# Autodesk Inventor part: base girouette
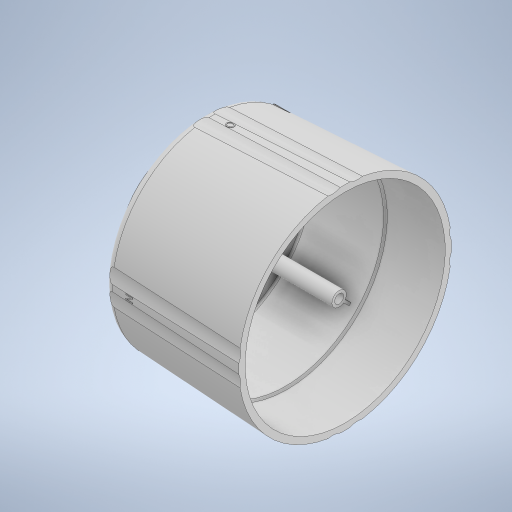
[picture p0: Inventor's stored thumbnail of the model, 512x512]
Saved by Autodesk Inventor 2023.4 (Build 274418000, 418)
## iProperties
Created: 2024-02
Part Number: base girouette
Material: Générique
Document SubType Name: Modeling
Designer: mel
Density: 1 g/cm^3
Appearance: Par défaut
Author: mel
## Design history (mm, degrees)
sketch "Esquisse1"
  geometry: L1 (1.75, 16.5)-(0, 16.5); L2 (0, 16.5)-(0, 15.5); L3 (6.57, 3)-(6.57, 15.5); L4 (6.57, 17.5)-(1.75, 17.5); L5 (1.75, 17.5)-(1.75, 16.5); L6 (45.5, 27.5)-(45.5, 29.25); L7 (45.5, 27.5)-(29.57, 27.5); L8 (30, 17.5)-(30, 16.5); L9 (9.57, 27)-(29.07, 27); L10 (30, 17.5)-(30, 16.5); L11 (9.07, 0)-(9.07, 27.382); L12 (45.5, 29.25)-(8.942, 27.375); L13 (29.57, 27.5)-(29.07, 27); L14 (29.57, 27.5)-(29.044, 27.5); L15 (0, 15.5)-(6.57, 15.5); L16 (-3.5, 0)-(9.07, 0) reference; L17 (0.5, 2.5)-(-3.5, 2.5); L18 (-3.5, 2.5)-(-3.5, 0); L19 (6.57, 3)-(0.5, 3); L20 (0.5, 3)-(0.5, 2.5); L21 (1.75, 2.5)-(4.57, 2.5); L22 (6.57, 24.878)-(6.57, 17.5); L23 (6.57, 15.5)-(6.57, 3); A1 r 2.5 centre (9.07, 24.878) between (8.942, 27.375) and (6.57, 24.878); A2 r 0.5 centre (9.57, 26.5) between (9.57, 27) and (9.07, 26.5); 3 further points
  constraints: 46 end point, 7 point on line, 6 horizontal, 6 parallel, 5 tangent, 4 perpendicular, 4 point on circle, 2 centre point
  dimensions: "d1" = 15.5 distance between parallel lines of L6 L8; "d5" = 27.25 vertical distance of point (6.5, 27.25) point (0, 0); "d6" = 2.5 radius of A1; "d7" = 0.5 radius of A2; "d8" = 135 deg angle of L13 L14; "d12" = 2.5 distance between parallel lines of L11 L3; "d14" = 15.5 distance from line of L15 point (0, 0); "d15" = 2.5 distance between parallel lines of L17 L16; "d17" = 4 distance between parallel lines of L20 L18; "d18" = 3 distance between parallel lines of L16 L19; "d22" = 27.5 distance between parallel lines of L7 L16; "d23" = 29.25 distance from line of L16 L6.end; "d29" = 2.93567 deg angle of L12 L16; "d63" = 27 distance between parallel lines of L16 L9; "d69" = 20 distance from line of L9.end L11
revolve "Révolution1" sketch "Esquisse1" stored, may be unused: angle "d19" = 90 deg
sketch "Esquisse2"
  geometry: C1 r 5 at (-3.5, 33.719); C2 r 27.5 at (0, 0) reference; C3 r 5 at (3.5, 33.709); 3 further points
  constraints: 2 centre point
  dimensions: "d20" = 3.5 horizontal distance of C1.centre point (0, 0); "d21" = 1.4 dimension on C2 C1; "d24" = 10 diameter of C1; "d25" = 10 diameter of C3; "d26" = 3.5 horizontal distance of C3.centre point (0, 0) (= d20)
extrude "Extrusion1" cut sketch "Esquisse2" stored distance "d27" = 10; taper "d28" = 2.93567 deg
pattern_circular "Réseau circulaire1" dims angle "d31" = 360 deg
node "Plan de construction1"
sketch "Esquisse4"
  geometry: L1 (-14.8, -0.779)-(-14.8, 1.573); L2 (-14.8, 1.573)-(-11.752, 1.573); L3 (-11.752, 1.573)-(-11.752, -0.779); L4 (-11.752, -0.779)-(-14.8, -0.779); L5 (-6.57, 24.878)-(-6.57, -24.878) reference; L6 (-9.57, 27)-(-9.57, -27) reference; L7 (-45.5, 28.868)-(-45.5, 4.736) reference; 1 further point
  constraints: 2 other
  dimensions: "d34" = 8.23 distance from line of L5 L1.start; "d38" = 3 distance between parallel lines of L5 L6 (derived); "d53" = 38.93019 distance between parallel lines of L7 L5 (derived); "d54" = 49.757 distance of L5.start L5.end (derived)
feature "Gravure1" sketch "Esquisse4" dims "d1" = 15.5, "d5" = 27.25, "d6" = 2.5, "d7" = 0.5, "d8" = 135 deg, "d12" = 2.5, "d14" = 15.5, "d15" = 2.5, "d17" = 4, "d18" = 3, "d22" = 27.5, "d23" = 29.25, "d29" = 0.51237, "d35" = 0.05, "d36" = 0, "d63" = 27, "d69" = 20
node "Plan de construction2"
sketch "Esquisse5"
  geometry: L1 (12.8, -0.899)-(12.8, 6.06); L2 (12.8, 6.06)-(18.657, 6.06); L3 (18.657, 6.06)-(18.657, -0.899); L4 (18.657, -0.899)-(12.8, -0.899); L5 (6.57, -24.878)-(6.57, 24.878) reference; 1 further point
  constraints: 2 other
  dimensions: "d39" = 6.23 distance between parallel lines of L1 L5
feature "Gravure2" sketch "Esquisse5" dims "d1" = 15.5, "d5" = 27.25, "d6" = 2.5, "d7" = 0.5, "d8" = 135 deg, "d12" = 2.5, "d14" = 15.5, "d15" = 2.5, "d17" = 4, "d18" = 3, "d22" = 27.5, "d23" = 29.25, "d29" = 0.51237, "d40" = 0.05 (= d35), "d41" = 0, "d63" = 27, "d69" = 20
node "Plan de construction3"
sketch "Esquisse6"
  geometry: L1 (-14.985, -0.963)-(-14.985, 0.983); L2 (-14.985, 0.983)-(-12.8, 0.983); L3 (-12.8, 0.983)-(-12.8, -0.963); L4 (-12.8, -0.963)-(-14.985, -0.963); L5 (-6.57, 24.878)-(-6.57, -24.878) reference; 1 further point
  constraints: 2 other
  dimensions: "d43" = 6.23 distance between parallel lines of L5 L3 (= d39)
feature "Gravure3" sketch "Esquisse6" dims "d1" = 15.5, "d5" = 27.25, "d6" = 2.5, "d7" = 0.5, "d8" = 135 deg, "d12" = 2.5, "d14" = 15.5, "d15" = 2.5, "d17" = 4, "d18" = 3, "d22" = 27.5, "d23" = 29.25, "d29" = 0.51237, "d44" = 0.05 (= d35), "d45" = 0, "d63" = 27, "d69" = 20
node "Plan de construction4"
node "Plan de construction6"
sketch "Esquisse11"
  geometry: L1 (-12.8, 0.751)-(-12.8, -0.781); L2 (-12.8, -0.781)-(-14.871, -0.781); L3 (-14.871, -0.781)-(-14.871, 0.751); L4 (-14.871, 0.751)-(-12.8, 0.751); L5 (-6.57, 24.878)-(-6.57, -24.878) reference; 1 further point
  constraints: 2 other
  dimensions: "d50" = 6.23 distance between parallel lines of L1 L5 (= d39)
feature "Gravure4" sketch "Esquisse11" dims "d1" = 15.5, "d5" = 27.25, "d6" = 2.5, "d7" = 0.5, "d8" = 135 deg, "d12" = 2.5, "d14" = 15.5, "d15" = 2.5, "d17" = 4, "d18" = 3, "d22" = 27.5, "d23" = 29.25, "d29" = 0.51237, "d51" = 0.05 (= d35), "d52" = 0, "d63" = 27, "d69" = 20
sketch "Esquisse12"
  geometry: L1 (-22.871, -0.25)-(14.435, 18.381); C1 r 2 at (14.435, 18.381); C2 r 2 at (16.784, -15.538); C3 r 2 at (-22.871, -0.25); C4 r 27 at (0, 0) reference; C5 r 26.5 at (0, 0) reference; 1 further point
  constraints: 3 centre point, 2 end point
  dimensions: "d55" = 30 dimension on C2 C1; "d56" = 37.7 dimension on C3 C1; "d57" = 38.5 dimension on C2 C3; "d58" = 4 diameter of C3; "d60" = 4 diameter of C1; "d61" = 4 diameter of C2; "d64" = 1.628 dimension on C1 C4; "d65" = 1.628 dimension on C5 C2 (= d64); "d66" = 1.62766 dimension on C3 C5 (derived); "d85" = 22.87098 horizontal distance of L1.start point (0, 0); "d86" = 23.372 distance of L1.end point (0, 0) (derived); "d87" = 22.872 distance of C2.centre point (0, 0) (derived); "d88" = 34 distance of C2.centre L1.end (derived); "d89" = 42.5 distance of C2.centre L1.start (derived)
extrude "Extrusion3" join sketch "Esquisse12" distance "d67" = 18; taper "d68" = 0 deg
sketch "Esquisse13"
  geometry: C1 r 2 at (-2.349, 33.919) reference; C2 r 2 at (0, 0) reference; C3 r 2 at (-39.655, 15.288) reference; 1 further point
hole "Perçage1" sketch "Esquisse13" at (-2.349, 33.919), (0, 0), (-39.655, 15.288) diameter "d70" = 2.5; stored, may be unused: countersink angle "d74" = 90 deg, drill point angle "d76" = 118 deg; dims "d71" = 20, "d72" = 4, "d73" = 2, "d75" = 18
sketch "Esquisse15"
  geometry: L1 (0, 0)-(-14.435, -18.381); L2 (0, 0)-(4.397, 5.599); L3 (0.997, 1.27)-(2.606, 3.319); L4 (2.606, 3.319)-(2.882, 3.103); L5 (2.882, 3.103)-(1.272, 1.054); L6 (1.272, 1.054)-(0.997, 1.27); L7 (0.997, 1.27)-(2.606, 3.319); L8 (2.606, 3.319)-(2.331, 3.535); L9 (2.331, 3.535)-(0.722, 1.486); L10 (0.722, 1.486)-(0.997, 1.27); L11 (-14.435, -18.381)-(-37.306, -18.631); L12 (-37.306, -18.631)-(-46.003, -18.726); L13 (-38.97, -18.649)-(-41.683, -18.679); L14 (-41.683, -18.679)-(-41.679, -19.029); L15 (-41.679, -19.029)-(-38.967, -18.999); L16 (-38.967, -18.999)-(-38.97, -18.649); L17 (-41.683, -18.679)-(-38.97, -18.649); L18 (-38.97, -18.649)-(-38.974, -18.299); L19 (-38.974, -18.299)-(-41.687, -18.329); L20 (-41.687, -18.329)-(-41.683, -18.679); L21 (-14.435, -18.381)-(2.349, -33.919); L22 (2.349, -33.919)-(9.232, -40.291); L23 (3.599, -35.076)-(5.881, -37.189); L24 (5.881, -37.189)-(5.643, -37.445); L25 (5.643, -37.445)-(3.361, -35.333); L26 (3.361, -35.333)-(3.599, -35.076); L27 (3.599, -35.076)-(5.881, -37.189); L28 (5.881, -37.189)-(6.119, -36.932); L29 (6.119, -36.932)-(3.837, -34.819); L30 (3.837, -34.819)-(3.599, -35.076); C1 r 2 at (0, 0) reference; C2 r 1.25 at (-37.306, -18.631) reference; C3 r 1.25 at (2.349, -33.919) reference
  constraints: 60 end point, 12 parallel, 9 point on line, 6 perpendicular, 3 collinear
  dimensions: "d77" = 0.35 distance of L3.end L4.end; "d78" = 0.35 distance of L8.end L3.end; "d81" = 0.35 distance of L14.end L13.end; "d82" = 0.35 distance of L18.end L13.start; "d83" = 0.35 distance of L23.end L24.end; "d84" = 0.35 distance of L28.end L23.end
extrude "Extrusion4" join sketch "Esquisse15" stored distance "d79" = 10; taper "d80" = 0 deg
node "Solide1"
node "Boucle projetée1"
node "Boucle projetée2"
other parameters: "d2" = 36.5, "d4" = 39, "d11" = 6.5
